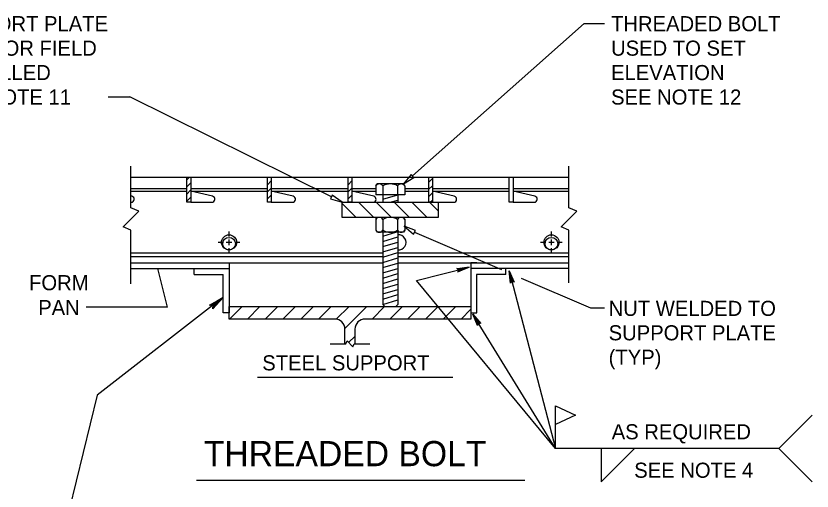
# Model space of a CAD drawing. Extents: x -24512 to -22484, y 4569 to 6351.
# Drawn here: x -23765.7 to -23607.6, y 5450.3 to 5544.7 of the extents above; entities that cross this region are included whole.
import ezdxf

# ---------------------------------------------------------------- set-up
doc = ezdxf.new("R2010")
doc.units = 0
for name, color, linetype in [('10', 7, 'Continuous'), ('3', 7, 'Continuous'), ('4', 7, 'Continuous'), ('5', 7, 'Continuous'), ('9', 7, 'Continuous')]:
    doc.layers.add(name, color=color, linetype=linetype)

# ---------------------------------------------------------------- blocks, each defined once
blk = doc.blocks.new('JUQ009')
at = {"layer": '3'}
for p, q in [((69.644875, 24.310375), (69.796125, 24.4615)), ((69.644875, 24.02525), (69.796125, 24.176375)), ((69.644875, 23.740125), (69.796125, 23.89125)), ((69.70425, 23.514375), (69.796125, 23.60625))]:
    blk.add_line(p, q, dxfattribs=at)
blk = doc.blocks.new('SYM009')
at = {"layer": '3'}
for p, q in [((66.419125, 24.506), (66.4355, 24.522375)), ((66.419125, 24.220875), (66.570375, 24.372125)), ((66.419125, 23.93575), (66.570375, 24.087)), ((66.419125, 23.650625), (66.570375, 23.801875)), ((66.567875, 23.514375), (66.570375, 23.51675))]:
    blk.add_line(p, q, dxfattribs=at)
blk = doc.blocks.new('SYM010')
at = {"layer": '3'}
for p, q in [((63.193375, 24.416625), (63.299125, 24.522375)), ((63.193375, 24.1315), (63.3445, 24.282625)), ((63.193375, 23.846375), (63.3445, 23.9975)), ((63.193375, 23.56125), (63.3445, 23.712375))]:
    blk.add_line(p, q, dxfattribs=at)
blk = doc.blocks.new('SYM011')
at = {"layer": '3'}
for p, q in [((89.35625, 63.69525), (89.860375, 64.19925)), ((90.069125, 63.69525), (90.573125, 64.19925)), ((90.781875, 63.69525), (91.285875, 64.19925)), ((91.49475, 63.69525), (91.99875, 64.19925)), ((92.2075, 63.69525), (92.7115, 64.19925)), ((92.920375, 63.69525), (93.424375, 64.19925)), ((93.628875, 63.691), (94.137125, 64.19925)), ((93.972625, 63.321875), (94.85, 64.19925)), ((95.05875, 63.69525), (95.56275, 64.19925)), ((95.7715, 63.69525), (96.275625, 64.19925)), ((96.484375, 63.69525), (96.988375, 64.19925)), ((97.197125, 63.69525), (97.70125, 64.19925)), ((97.91, 63.69525), (98.414, 64.19925)), ((98.62275, 63.69525), (99.014, 64.0865)), ((94.121125, 62.757625), (94.377, 63.013375))]:
    blk.add_line(p, q, dxfattribs=at)
blk = doc.blocks.new('SYM021')
at = {"layer": '3'}
for p, q in [((57.808, 114.691375), (57.2555, 115.243875)), ((58.52075, 114.691375), (57.916, 115.29625)), ((59.233625, 114.691375), (58.62875, 115.29625)), ((59.946375, 114.691375), (59.341625, 115.29625)), ((60.65925, 114.691375), (60.054375, 115.29625)), ((61.101375, 114.962), (60.76725, 115.29625))]:
    blk.add_line(p, q, dxfattribs=at)

msp = doc.modelspace()

# ---------------------------------------------------------------- linework, layer by layer
at = {"layer": '10'}
for p, q in [((-23686.19, 5492.18), (-23675.75, 5494.79)), ((-23658.57, 5458.77), (-23686.19, 5492.18)), ((-23658.57, 5458.77), (-23675.01, 5485.47)), ((-23664.64, 5452.46), (-23729.86, 5452.46))]:
    msp.add_line(p, q, dxfattribs=at)
for points in [[(-23678.06, 5494.51), (-23677.94, 5494.37), (-23675.75, 5494.79), (-23678.06, 5494.51), (-23678.2, 5494.58), (-23675.75, 5494.79), (-23677.88, 5494.14), (-23677.92, 5493.96), (-23675.75, 5494.79), (-23678.01, 5493.82), (-23677.92, 5493.96)], [(-23667.46, 5491.79), (-23667.32, 5491.92), (-23667.76, 5494.1), (-23667.46, 5491.79), (-23667.53, 5491.65), (-23667.76, 5494.1), (-23667.1, 5491.98), (-23666.92, 5491.94), (-23667.76, 5494.1), (-23666.78, 5491.85), (-23666.92, 5491.94)], [(-23727.05, 5487.28), (-23726.83, 5487.18), (-23724.55, 5488.8), (-23727.05, 5487.28), (-23727.24, 5487.29), (-23724.55, 5488.8), (-23726.65, 5486.96), (-23726.6, 5486.73), (-23724.55, 5488.8), (-23726.64, 5486.52), (-23726.6, 5486.73)], [(-23674.04, 5483.35), (-23673.95, 5483.51), (-23675.01, 5485.47), (-23674.04, 5483.35), (-23674.07, 5483.2), (-23675.01, 5485.47), (-23673.75, 5483.64), (-23673.57, 5483.66), (-23675.01, 5485.47), (-23673.41, 5483.61), (-23673.57, 5483.66)]]:
    msp.add_lwpolyline(points, dxfattribs=at)
at = {"layer": '4'}
for p, q in [((-23742.86, 5512.7), (-23731.76, 5512.7)), ((-23731.01, 5512.7), (-23715.76, 5512.7)), ((-23715.01, 5512.7), (-23699.76, 5512.7)), ((-23699.01, 5512.7), (-23683.76, 5512.7)), ((-23683.01, 5512.7), (-23667.76, 5512.7)), ((-23667.01, 5512.7), (-23655.92, 5512.7)), ((-23742.86, 5510.44), (-23731.76, 5510.44)), ((-23731.01, 5510.44), (-23715.76, 5510.44)), ((-23715.01, 5510.44), (-23699.76, 5510.44)), ((-23699.01, 5510.44), (-23694.27, 5510.44)), ((-23694.27, 5510.98), (-23693.98, 5511.36)), ((-23694.27, 5510.98), (-23694.27, 5509.19)), ((-23688.79, 5511.36), (-23693.98, 5511.36)), ((-23692.83, 5510.98), (-23692.83, 5509.19)), ((-23689.94, 5510.98), (-23689.94, 5509.19)), ((-23688.5, 5510.98), (-23688.79, 5511.36)), ((-23688.5, 5510.98), (-23688.5, 5509.19)), ((-23688.5, 5510.44), (-23683.76, 5510.44)), ((-23683.01, 5510.44), (-23667.76, 5510.44)), ((-23667.01, 5510.44), (-23655.92, 5510.44)), ((-23742.86, 5509.94), (-23731.76, 5509.94)), ((-23742.67, 5508.9), (-23742.86, 5508.95)), ((-23731.01, 5509.94), (-23715.76, 5509.94)), ((-23726.67, 5508.9), (-23731.01, 5509.94)), ((-23715.01, 5509.94), (-23699.76, 5509.94)), ((-23710.67, 5508.9), (-23715.01, 5509.94)), ((-23699.01, 5509.94), (-23694.27, 5509.94)), ((-23694.67, 5508.9), (-23699.01, 5509.94)), ((-23688.5, 5509.19), (-23694.27, 5509.19)), ((-23692.89, 5509.19), (-23692.89, 5507.7)), ((-23689.89, 5509.19), (-23689.89, 5507.7)), ((-23688.5, 5509.94), (-23683.76, 5509.94)), ((-23683.01, 5509.94), (-23667.76, 5509.94)), ((-23678.67, 5508.9), (-23683.01, 5509.94)), ((-23667.01, 5509.94), (-23655.92, 5509.94)), ((-23662.67, 5508.9), (-23667.01, 5509.94)), ((-23742.86, 5507.7), (-23742.79, 5507.7)), ((-23731.01, 5507.7), (-23726.79, 5507.7)), ((-23715.01, 5507.7), (-23710.8, 5507.7)), ((-23699.01, 5507.7), (-23694.8, 5507.7)), ((-23683.01, 5507.7), (-23678.8, 5507.7)), ((-23667.01, 5507.7), (-23662.8, 5507.7)), ((-23694.27, 5504.32), (-23693.98, 5504.7)), ((-23694.27, 5504.32), (-23694.27, 5502.14)), ((-23688.79, 5504.7), (-23693.98, 5504.7)), ((-23692.83, 5504.32), (-23692.83, 5502.14)), ((-23689.94, 5504.32), (-23689.94, 5502.14)), ((-23688.5, 5504.32), (-23688.79, 5504.7)), ((-23688.5, 5504.32), (-23688.5, 5502.14)), ((-23694.27, 5502.14), (-23693.98, 5501.76)), ((-23688.5, 5502.14), (-23688.79, 5501.76)), ((-23688.79, 5501.76), (-23693.98, 5501.76)), ((-23692.89, 5501.76), (-23692.89, 5487.42)), ((-23689.89, 5501.76), (-23689.89, 5487.42)), ((-23742.86, 5497.69), (-23692.89, 5497.69)), ((-23689.89, 5497.69), (-23655.92, 5497.69)), ((-23742.86, 5496.95), (-23692.89, 5496.95)), ((-23689.89, 5496.95), (-23655.92, 5496.95)), ((-23742.86, 5495.7), (-23692.89, 5495.7)), ((-23742.86, 5494.54), (-23723.39, 5494.54)), ((-23730.33, 5493.39), (-23730.33, 5494.54)), ((-23724.54, 5495.7), (-23723.39, 5495.7)), ((-23723.39, 5495.7), (-23723.39, 5485.76)), ((-23689.89, 5495.7), (-23655.92, 5495.7)), ((-23675.39, 5495.7), (-23675.39, 5485.76)), ((-23674.23, 5495.7), (-23675.39, 5495.7)), ((-23655.94, 5494.54), (-23675.39, 5494.54)), ((-23668.46, 5493.39), (-23668.46, 5494.54)), ((-23730.33, 5493.39), (-23724.54, 5493.39)), ((-23724.54, 5485.76), (-23724.54, 5493.39)), ((-23668.46, 5493.39), (-23674.25, 5493.39)), ((-23674.23, 5485.76), (-23674.23, 5493.39)), ((-23723.39, 5484.51), (-23723.39, 5487.01)), ((-23723.39, 5487.01), (-23675.39, 5487.01)), ((-23692.48, 5487.01), (-23692.89, 5487.42)), ((-23690.3, 5487.01), (-23689.89, 5487.42)), ((-23675.39, 5487.01), (-23675.39, 5484.51)), ((-23723.39, 5485.76), (-23724.54, 5485.76)), ((-23675.39, 5485.76), (-23674.23, 5485.76)), ((-23702.39, 5484.51), (-23723.39, 5484.51)), ((-23675.39, 5484.51), (-23696.39, 5484.51)), ((-23700.39, 5479.59), (-23700.39, 5482.51)), ((-23698.39, 5482.51), (-23698.39, 5479.59)), ((-23703.33, 5479.59), (-23700.39, 5479.59)), ((-23698.39, 5479.59), (-23695.44, 5479.59))]:
    msp.add_line(p, q, dxfattribs=at)
for points in [[(-23742.86, 5491.49), (-23742.86, 5502.18), (-23744.41, 5502.82), (-23741.31, 5505.92), (-23742.86, 5506.57), (-23742.86, 5514.88)], [(-23655.92, 5491.68), (-23655.92, 5502.18), (-23657.47, 5502.82), (-23654.36, 5505.92), (-23655.92, 5506.57), (-23655.92, 5514.88)], [(-23700.39, 5479.59), (-23700.21, 5479.59), (-23699.97, 5480.17), (-23698.8, 5479.01), (-23698.56, 5479.59), (-23698.39, 5479.59)]]:
    msp.add_lwpolyline(points, dxfattribs=at)
for points in [[(-23731.01, 5512.7), (-23731.01, 5507.7), (-23731.76, 5507.7), (-23731.76, 5512.7)], [(-23715.01, 5512.7), (-23715.01, 5507.7), (-23715.76, 5507.7), (-23715.76, 5512.7)], [(-23699.01, 5512.7), (-23699.01, 5507.7), (-23699.76, 5507.7), (-23699.76, 5512.7)], [(-23683.01, 5512.7), (-23683.01, 5507.7), (-23683.76, 5507.7), (-23683.76, 5512.7)], [(-23667.01, 5512.7), (-23667.01, 5507.7), (-23667.76, 5507.7), (-23667.76, 5512.7)], [(-23700.92, 5507.7), (-23681.85, 5507.7), (-23681.85, 5504.7), (-23700.92, 5504.7)]]:
    msp.add_lwpolyline(points, close=True, dxfattribs=at)
for centre, radius in [((-23723.39, 5499.74), 1.5), ((-23723.39, 5499.49), 1.25), ((-23659.39, 5499.74), 1.5), ((-23659.39, 5499.49), 1.25)]:
    msp.add_circle(centre, radius, dxfattribs=at)
for centre, radius, start, end in [((-23693.55, 5510.48), 0.876, 34.4962, 145.5038), ((-23691.39, 5508.42), 2.93, 60.5208, 119.4792), ((-23689.22, 5510.48), 0.876, 34.4962, 145.5038), ((-23742.81, 5508.31), 0.61, 271.249, 76.5605), ((-23726.81, 5508.31), 0.61, 271.249, 76.5605), ((-23710.81, 5508.31), 0.61, 271.249, 76.5605), ((-23694.81, 5508.31), 0.61, 271.249, 76.5605), ((-23678.81, 5508.31), 0.61, 271.249, 76.5605), ((-23662.81, 5508.31), 0.61, 271.249, 76.5605), ((-23693.55, 5503.82), 0.876, 34.4962, 145.5038), ((-23691.39, 5501.76), 2.93, 60.5208, 119.4792), ((-23689.22, 5503.82), 0.876, 34.4962, 145.5038), ((-23693.55, 5502.63), 0.876, 214.4962, 325.5038), ((-23691.39, 5504.69), 2.93, 240.5208, 299.4792), ((-23689.22, 5502.63), 0.876, 214.4962, 325.5038), ((-23689.74, 5499.74), 1.5, 264.5171, 95.4829), ((-23702.39, 5482.51), 2, 0, 90), ((-23696.39, 5482.51), 2, 90, 180)]:
    msp.add_arc(centre, radius, start, end, dxfattribs=at)
at = {"layer": '5'}
for p, q in [((-23692.89, 5508.29), (-23689.89, 5509.19)), ((-23691.39, 5507.7), (-23689.89, 5508.14)), ((-23692.89, 5500.99), (-23690.3, 5501.76)), ((-23692.89, 5499.94), (-23689.89, 5500.84)), ((-23692.89, 5498.9), (-23689.89, 5499.8)), ((-23692.89, 5497.86), (-23689.89, 5498.75)), ((-23692.89, 5496.81), (-23689.89, 5497.71)), ((-23692.89, 5495.77), (-23689.89, 5496.66)), ((-23692.89, 5494.73), (-23689.89, 5495.62)), ((-23692.89, 5493.68), (-23689.89, 5494.58)), ((-23692.89, 5492.64), (-23689.89, 5493.53)), ((-23692.89, 5491.6), (-23689.89, 5492.49)), ((-23692.89, 5490.55), (-23689.89, 5491.45)), ((-23692.89, 5489.51), (-23689.89, 5490.4)), ((-23692.89, 5488.47), (-23689.89, 5489.36)), ((-23692.89, 5487.42), (-23689.89, 5488.32))]:
    msp.add_line(p, q, dxfattribs=at)
at = {"layer": '9'}
for p, q in [((-23687, 5512.95), (-23652.89, 5543.24)), ((-23652.89, 5543.24), (-23648.85, 5543.24)), ((-23747.39, 5528.67), (-23743.07, 5528.67)), ((-23703.07, 5508.76), (-23743.07, 5528.67)), ((-23723.39, 5500.88), (-23723.39, 5501.89)), ((-23686.57, 5501.75), (-23669.31, 5494.34)), ((-23659.39, 5500.88), (-23659.39, 5501.89)), ((-23724.52, 5499.74), (-23725.54, 5499.74)), ((-23722.84, 5499.74), (-23723.93, 5499.74)), ((-23723.39, 5499.2), (-23723.39, 5500.28)), ((-23721.23, 5499.74), (-23722.25, 5499.74)), ((-23660.53, 5499.74), (-23661.54, 5499.74)), ((-23658.84, 5499.74), (-23659.93, 5499.74)), ((-23659.39, 5499.2), (-23659.39, 5500.28)), ((-23657.23, 5499.74), (-23658.25, 5499.74)), ((-23723.39, 5497.58), (-23723.39, 5498.6)), ((-23659.39, 5497.58), (-23659.39, 5498.6)), ((-23735.64, 5486.84), (-23737.51, 5494.54)), ((-23667.76, 5494.1), (-23658.57, 5458.77)), ((-23665.42, 5492.66), (-23651.61, 5486.73)), ((-23724.88, 5488.56), (-23749.57, 5469.36)), ((-23735.64, 5486.84), (-23751.75, 5486.84)), ((-23651.61, 5486.73), (-23648.82, 5486.73)), ((-23717.72, 5472.94), (-23678.94, 5472.94)), ((-23749.57, 5469.36), (-23757.41, 5437.2)), ((-23658.57, 5458.77), (-23658.57, 5467.26)), ((-23607.64, 5465.39), (-23614.26, 5458.77)), ((-23614.26, 5458.77), (-23658.57, 5458.77)), ((-23649.52, 5458.77), (-23649.52, 5452.15)), ((-23649.52, 5452.15), (-23642.9, 5458.77)), ((-23607.64, 5452.15), (-23614.26, 5458.77))]:
    msp.add_line(p, q, dxfattribs=at)
for points in [[(-23686.73, 5512.65), (-23687.26, 5513.25), (-23688.79, 5511.36)], [(-23702.89, 5509.12), (-23703.25, 5508.41), (-23700.92, 5507.7)], [(-23686.77, 5501.4), (-23686.37, 5502.1), (-23688.64, 5502.96)], [(-23658.57, 5467.26), (-23654.63, 5465.4), (-23658.57, 5463.54)]]:
    msp.add_lwpolyline(points, close=True, dxfattribs=at)

# ---------------------------------------------------------------- block references
at = {"layer": '3'}
for name, p, xscale, yscale in [('SYM010', (-24045.19, 5391.07), 4.959842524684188, 4.959842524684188), ('SYM009', (-24045.19, 5391.07), 4.959842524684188, 4.959842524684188), ('SYM009', (-24029.19, 5391.07), 4.959842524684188, 4.959842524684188), ('JUQ009', (-24029.19, 5391.07), 4.959842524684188, 4.959842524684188), ('SYM021', (-23984.9, 4935.84), 4.95984251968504, 4.95984251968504), ('SYM011', (-24166.48, 5168.59), 4.959842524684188, 4.959842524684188)]:
    msp.add_blockref(name, p, dxfattribs=dict(at, xscale=xscale, yscale=yscale))

# ---------------------------------------------------------------- texts
at = {"layer": '9'}
for s, height, p in [('SUPPORT PLATE', 2.9999, (-23780.63, 5541.68)), ('THREADED BOLT', 2.9999, (-23647.55, 5541.68)), ('SHOP OR FIELD', 2.9999, (-23780.63, 5536.82)), ('USED TO SET ', 2.9999, (-23647.55, 5536.82)), ('INSTALLED', 3, (-23780.63, 5531.97)), ('ELEVATION', 3, (-23647.55, 5531.97)), ('SEE NOTE 11', 2.9999, (-23780.63, 5527.11)), ('SEE NOTE 12', 2.9999, (-23647.55, 5527.11)), (' FORM', 3, (-23764.21, 5490.23)), ('PAN', 3, (-23761.28, 5485.29)), ('NUT WELDED TO', 2.9999, (-23648.03, 5485.13)), ('SUPPORT PLATE', 2.9999, (-23648.03, 5480.28)), ('(TYP)', 3, (-23648.03, 5475.42)), ('STEEL SUPPORT', 2.9999, (-23716.8, 5474.31)), ('AS REQUIRED', 2.9999, (-23647.42, 5460.62)), ('THREADED BOLT', 5, (-23728.4, 5455.28)), ('SEE NOTE 4', 3, (-23642.95, 5452.98))]:
    msp.add_text(s, height=height, dxfattribs=at).set_placement(p)

doc.saveas('drawing.dxf')
